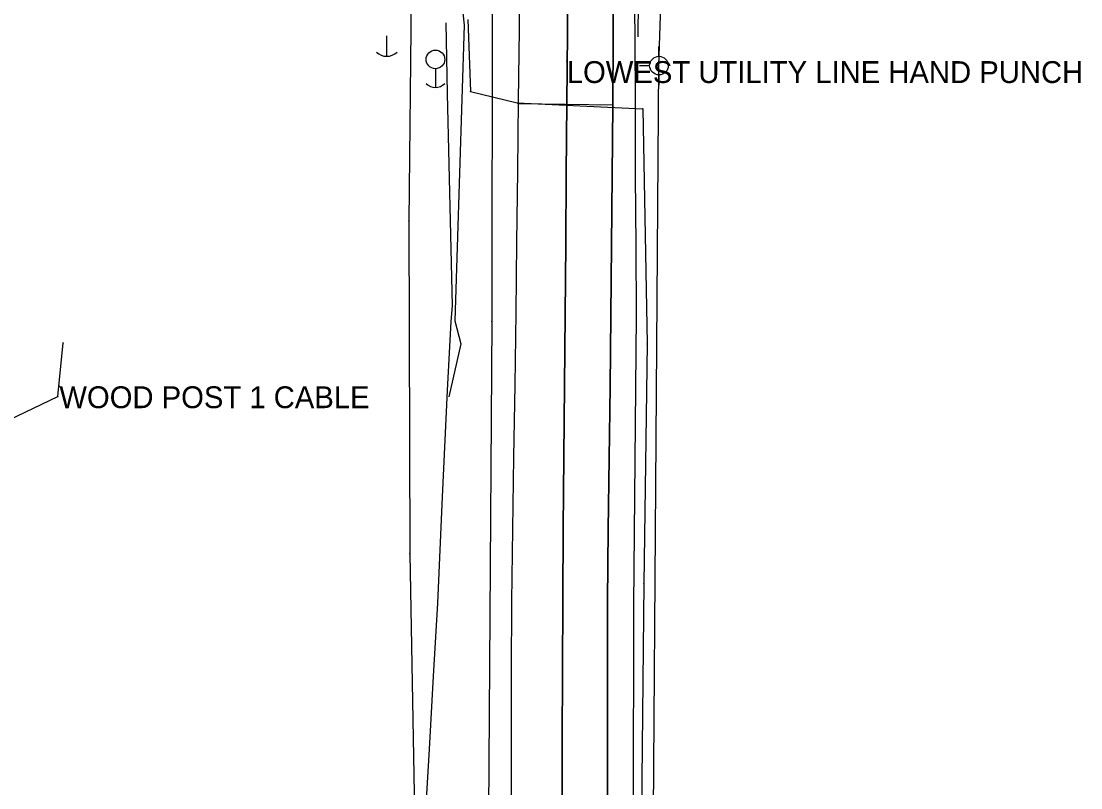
# Model space of a CAD drawing. Extents: x 1707085 to 1720058, y 548761 to 560063.
# Drawn here: x 1712356.6 to 1712599, y 550251.1 to 550426.5 of the extents above; entities that cross this region are included whole.
import ezdxf

# ---------------------------------------------------------------- set-up
doc = ezdxf.new("R2010")
doc.units = 0
for name, color, linetype in [('44', 7, 'Continuous'), ('R_Contours', 7, 'Continuous'), ('R_Water Annot', 7, 'Continuous'), ('S_EDGE_PAVEMENT', 7, 'Continuous'), ('S_ELECTRIC_UTILITIES_ANNOT', 7, 'Continuous'), ('S_GAS_UTILITIES', 7, 'Continuous'), ('S_MSC_PT_SYM', 7, 'Continuous'), ('S_PAVEMENT_CROWN', 7, 'Continuous'), ('S_SANITARY_SEWER', 7, 'Continuous'), ('S_SURVEY_TEXT_ANNOT', 7, 'Continuous'), ('S_UTILITY_POLE', 7, 'Continuous'), ('S_UTL_PT_SYM', 7, 'Continuous')]:
    doc.layers.add(name, color=color, linetype=linetype)

msp = doc.modelspace()

# ---------------------------------------------------------------- linework, layer by layer
for points in [[(1712499.77, 550680.44), (1712499.76, 550665.56), (1712499.74, 550650.67), (1712499.72, 550635.78), (1712499.71, 550620.89), (1712499.63, 550603.25), (1712499.55, 550585.61), (1712499.47, 550567.97), (1712499.4, 550550.32), (1712499.11, 550534.87), (1712498.82, 550519.41), (1712498.53, 550503.95), (1712498.24, 550488.49), (1712498.1, 550472.1), (1712497.96, 550455.71), (1712497.82, 550439.31), (1712497.69, 550422.92)], [(1712450.26, 550546.06), (1712450.63, 550530.87), (1712451.01, 550515.67), (1712451.38, 550500.48), (1712451.76, 550485.28), (1712453.29, 550470.36), (1712454.82, 550455.43), (1712456.35, 550440.5), (1712457.89, 550425.57), (1712457.37, 550408.66), (1712456.85, 550391.74), (1712456.33, 550374.83), (1712455.82, 550357.92), (1712457.14, 550352.68), (1712454.4, 550340.57)], [(1712496.71, 550439.33), (1712496.93, 550423.15), (1712497.01, 550407.13), (1712497.08, 550391.12), (1712497.16, 550375.1), (1712497.24, 550359.08), (1712497.1, 550342.54), (1712496.96, 550326), (1712496.82, 550309.45), (1712496.69, 550292.91), (1712496.65, 550277.21), (1712496.61, 550261.52), (1712496.57, 550245.82)], [(1712453.7, 550426.13), (1712454.07, 550409.95), (1712454.43, 550393.78), (1712454.8, 550377.6), (1712455.16, 550361.42), (1712454.85, 550357.79), (1712454.04, 550341.99), (1712452.93, 550317.67), (1712451.83, 550293.35), (1712450.86, 550276.67), (1712449.89, 550259.99), (1712448.93, 550243.31), (1712447.96, 550226.63), (1712448.47, 550211.31), (1712448.98, 550195.99), (1712449.49, 550180.67), (1712450, 550165.35), (1712449.84, 550141.04), (1712449.68, 550116.73), (1712449.05, 550102.59), (1712448.43, 550088.44)]]:
    msp.add_lwpolyline(points)
at = {"layer": '44'}
for p, q in [((1712464.32, 550556.31), (1712464.29, 550357.8)), ((1712464.29, 550357.8), (1712462.99, 550181.46))]:
    msp.add_line(p, q, dxfattribs=at)
at = {"layer": 'R_Contours'}
for points in [[(1712364.98, 550340.67), (1712366.16, 550352.9)], [(1712335.34, 550326.5), (1712364.98, 550340.67)]]:
    msp.add_lwpolyline(points, dxfattribs=at)
at = {"layer": 'R_Water Annot'}
for p, q in [((1712446.43, 550484.44), (1712445.25, 550380.8)), ((1712445.25, 550380.8), (1712445.5, 550304.66)), ((1712445.5, 550304.66), (1712446.83, 550231.45))]:
    msp.add_line(p, q, dxfattribs=at)
at = {"layer": 'S_EDGE_PAVEMENT'}
for points in [[(1712470.52, 550439.9), (1712470.48, 550424.59), (1712470.3, 550408.39), (1712470.11, 550392.19), (1712469.93, 550375.99), (1712469.75, 550359.79), (1712469.49, 550343.3), (1712469.24, 550326.8), (1712468.98, 550310.3), (1712468.73, 550293.81), (1712468.7, 550277.69), (1712468.67, 550261.56), (1712468.64, 550245.44)], [(1712492.11, 550439.15), (1712492.04, 550423.35), (1712491.91, 550407.31), (1712491.78, 550391.26), (1712491.64, 550375.22), (1712491.51, 550359.17), (1712491.3, 550342.86), (1712491.1, 550326.54), (1712490.89, 550310.22), (1712490.68, 550293.9), (1712490.7, 550277.75), (1712490.72, 550261.61), (1712490.74, 550245.46)], [(1712490.74, 550245.46), (1712490.72, 550261.61), (1712490.7, 550277.75), (1712490.68, 550293.9), (1712490.89, 550310.22), (1712491.1, 550326.54), (1712491.3, 550342.86), (1712491.51, 550359.17), (1712491.64, 550375.22), (1712491.78, 550391.26), (1712491.91, 550407.31), (1712492.04, 550423.35), (1712492.11, 550439.15)]]:
    msp.add_lwpolyline(points, dxfattribs=at)
at = {"layer": 'S_GAS_UTILITIES'}
for p, q in [((1712458.76, 550426.92), (1712459.4, 550410.41)), ((1712459.4, 550410.41), (1712470.08, 550407.84)), ((1712470.08, 550407.84), (1712498.79, 550406.46)), ((1712498.79, 550406.46), (1712499.78, 550352.68)), ((1712499.78, 550352.68), (1712499.04, 550297.85)), ((1712499.04, 550297.85), (1712498.41, 550239.12))]:
    msp.add_line(p, q, dxfattribs=at)
at = {"layer": 'S_MSC_PT_SYM'}
for points in [[(1712366.16, 550352.9), (1712366.16, 550352.95), (1712366.16, 550352.9), (1712366.11, 550352.9), (1712366.16, 550352.9), (1712366.16, 550352.85), (1712366.16, 550352.9), (1712366.21, 550352.9)], [(1712365.32, 550342.98), (1712365.32, 550343.03), (1712365.32, 550342.98), (1712365.27, 550342.98), (1712365.32, 550342.98), (1712365.32, 550342.93), (1712365.32, 550342.98), (1712365.37, 550342.98)], [(1712364.98, 550340.67), (1712364.98, 550340.72), (1712364.98, 550340.67), (1712364.93, 550340.67), (1712364.98, 550340.67), (1712364.98, 550340.62), (1712364.98, 550340.67), (1712365.03, 550340.67)]]:
    msp.add_lwpolyline(points, dxfattribs=at)
at = {"layer": 'S_PAVEMENT_CROWN'}
for points in [[(1712480.34, 550245.4), (1712480.38, 550261.69), (1712480.43, 550277.99), (1712480.48, 550294.28), (1712480.61, 550310.56), (1712480.75, 550326.85), (1712480.88, 550343.13), (1712481.02, 550359.41), (1712481.15, 550375.53), (1712481.28, 550391.64), (1712481.41, 550407.75), (1712481.54, 550423.86), (1712481.65, 550439.32)], [(1712481.65, 550439.32), (1712481.54, 550423.86), (1712481.41, 550407.75), (1712481.28, 550391.64), (1712481.15, 550375.53), (1712481.02, 550359.41), (1712480.88, 550343.13), (1712480.75, 550326.85), (1712480.61, 550310.56), (1712480.48, 550294.28), (1712480.43, 550277.99), (1712480.38, 550261.69), (1712480.34, 550245.4)]]:
    msp.add_lwpolyline(points, dxfattribs=at)
at = {"layer": 'S_SANITARY_SEWER'}
msp.add_line((1712491.88, 550407.32), (1712470.25, 550407.61), dxfattribs=at)
at = {"layer": 'S_UTILITY_POLE'}
for p, q in [((1712440.15, 550423.18), (1712440.15, 550418.46)), ((1712502.49, 550418.45), (1712502.49, 550420.7)), ((1712451.36, 550415.58), (1712451.36, 550411.35)), ((1712500.4, 550416.32), (1712498.07, 550416.32)), ((1712502.57, 550411.9), (1712502.57, 550414.23))]:
    msp.add_line(p, q, dxfattribs=at)
msp.add_lwpolyline([(1712497.7, 549518.48), (1712500.91, 549949.57), (1712500.58, 550149.34), (1712502.49, 550416.34), (1712509.79, 550634.49), (1712512.76, 550903.53), (1712513.37, 551033.49), (1712513.87, 551133.13), (1712444.45, 551132.54)], dxfattribs=at)
for centre in [(1712451.35, 550417.76), (1712502.49, 550416.34)]:
    msp.add_circle(centre, 2.13, dxfattribs=at)
for centre, radius in [((1712440.21, 550421.88), 3.41), ((1712451.35, 550414.46), 3.09)]:
    msp.add_arc(centre, radius, 226.3972, 313.6028, dxfattribs=at)
at = {"layer": 'S_UTL_PT_SYM'}
for points in [[(1712481.4, 550417.36), (1712481.4, 550417.41), (1712481.4, 550417.36), (1712481.35, 550417.36), (1712481.4, 550417.36), (1712481.4, 550417.31), (1712481.4, 550417.36), (1712481.45, 550417.36)], [(1712481.46, 550415.85), (1712481.46, 550415.9), (1712481.46, 550415.85), (1712481.41, 550415.85), (1712481.46, 550415.85), (1712481.46, 550415.8), (1712481.46, 550415.85), (1712481.51, 550415.85)], [(1712459.4, 550410.41), (1712459.4, 550410.46), (1712459.4, 550410.41), (1712459.35, 550410.41), (1712459.4, 550410.41), (1712459.4, 550410.36), (1712459.4, 550410.41), (1712459.45, 550410.41)], [(1712470.08, 550407.84), (1712470.08, 550407.89), (1712470.08, 550407.84), (1712470.03, 550407.84), (1712470.08, 550407.84), (1712470.08, 550407.79), (1712470.08, 550407.84), (1712470.13, 550407.84)], [(1712470.25, 550407.61), (1712470.25, 550407.66), (1712470.25, 550407.61), (1712470.2, 550407.61), (1712470.25, 550407.61), (1712470.25, 550407.56), (1712470.25, 550407.61), (1712470.3, 550407.61)], [(1712491.88, 550407.32), (1712491.88, 550407.37), (1712491.88, 550407.32), (1712491.83, 550407.32), (1712491.88, 550407.32), (1712491.88, 550407.27), (1712491.88, 550407.32), (1712491.93, 550407.32)], [(1712498.79, 550406.46), (1712498.79, 550406.51), (1712498.79, 550406.46), (1712498.74, 550406.46), (1712498.79, 550406.46), (1712498.79, 550406.41), (1712498.79, 550406.46), (1712498.84, 550406.46)], [(1712445.25, 550380.8), (1712445.25, 550380.85), (1712445.25, 550380.8), (1712445.2, 550380.8), (1712445.25, 550380.8), (1712445.25, 550380.75), (1712445.25, 550380.8), (1712445.3, 550380.8)], [(1712464.29, 550357.8), (1712464.29, 550357.85), (1712464.29, 550357.8), (1712464.24, 550357.8), (1712464.29, 550357.8), (1712464.29, 550357.75), (1712464.29, 550357.8), (1712464.34, 550357.8)], [(1712499.78, 550352.68), (1712499.78, 550352.73), (1712499.78, 550352.68), (1712499.73, 550352.68), (1712499.78, 550352.68), (1712499.78, 550352.63), (1712499.78, 550352.68), (1712499.83, 550352.68)], [(1712445.5, 550304.66), (1712445.5, 550304.71), (1712445.5, 550304.66), (1712445.45, 550304.66), (1712445.5, 550304.66), (1712445.5, 550304.61), (1712445.5, 550304.66), (1712445.55, 550304.66)], [(1712499.04, 550297.85), (1712499.04, 550297.9), (1712499.04, 550297.85), (1712498.99, 550297.85), (1712499.04, 550297.85), (1712499.04, 550297.8), (1712499.04, 550297.85), (1712499.09, 550297.85)]]:
    msp.add_lwpolyline(points, dxfattribs=at)

# ---------------------------------------------------------------- texts
at = {"layer": 'S_ELECTRIC_UTILITIES_ANNOT'}
msp.add_text('LOWEST UTILITY LINE HAND PUNCH', height=5, dxfattribs=at).set_placement((1712481.4, 550412.36))
at = {"layer": 'S_SURVEY_TEXT_ANNOT'}
msp.add_text('WOOD POST 1 CABLE', height=5, dxfattribs=at).set_placement((1712365.32, 550337.98))

doc.saveas('drawing.dxf')
